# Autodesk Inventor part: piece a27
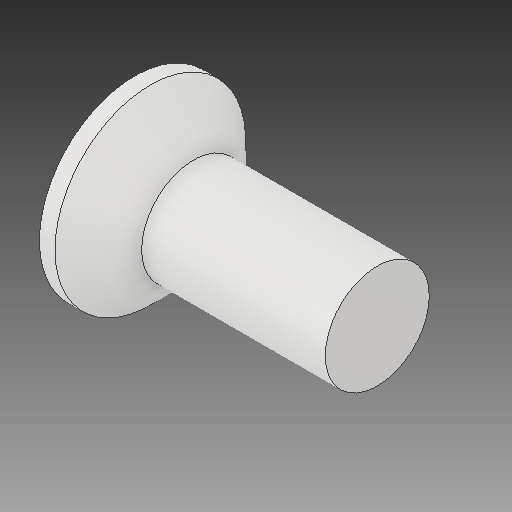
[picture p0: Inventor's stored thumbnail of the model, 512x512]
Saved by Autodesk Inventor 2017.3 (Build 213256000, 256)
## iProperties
Created: 1999-08
Part Number: piece a27
Material: solidworks materials|Alliage 7079|22
Document SubType Name: Modeling
Designer: ficho
Density: 2.7 g/cm^3
Appearance: 255,255,255
Author: ficho
Sending System: SolidWorks 2009
Last Author: christophe
Last Saved: 2011-01-17
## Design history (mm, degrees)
feature "CirPattern1"
node "Solide1"
